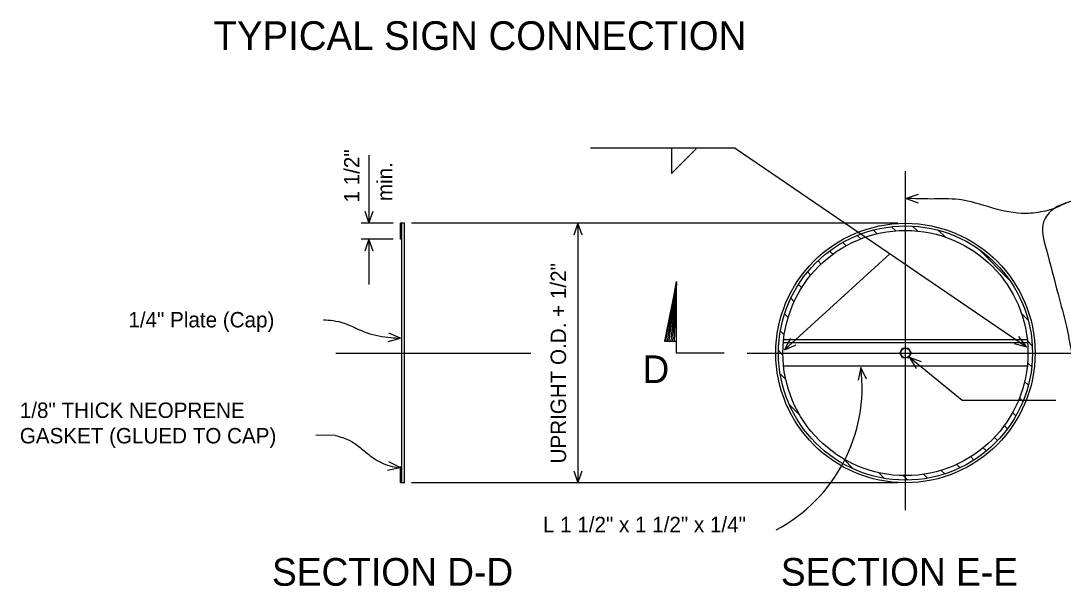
# Model space of a CAD drawing. Extents: x -211.3 to -203.73, y 425.09 to 430.2.
# Drawn here: x -206.732 to -205.177, y 426.831 to 427.674 of the extents above; entities that cross this region are included whole.
import ezdxf

# ---------------------------------------------------------------- set-up
doc = ezdxf.new("R2010")
doc.units = 0
doc.layers.add('Level 1', color=7, linetype='Continuous')
doc.layers.add('Level 2', color=7, linetype='Continuous')

msp = doc.modelspace()

# ---------------------------------------------------------------- linework, layer by layer
at = {"layer": 'Level 1'}
for p, q in [((-206.1595, 427.3722), (-206.1654, 427.3722)), ((-206.1654, 427.3485), (-206.1654, 427.3722)), ((-206.1634, 426.985), (-206.1634, 427.3722)), ((-206.1595, 426.985), (-206.1595, 427.3722)), ((-205.4543, 427.3566), (-205.4598, 427.3621)), ((-205.4265, 427.361), (-205.4326, 427.3671)), ((-205.394, 427.3607), (-205.4013, 427.3679)), ((-205.3529, 427.3518), (-205.363, 427.3618)), ((-206.1634, 427.3485), (-206.1654, 427.3485)), ((-205.5006, 427.3386), (-205.5055, 427.3435)), ((-205.4788, 427.3489), (-205.4839, 427.3541)), ((-205.5203, 427.3261), (-205.525, 427.3308)), ((-205.2575, 427.2885), (-205.3022, 427.3331)), ((-205.5378, 427.3114), (-205.5425, 427.3161)), ((-205.5533, 427.2947), (-205.558, 427.2995)), ((-205.5668, 427.2761), (-205.5716, 427.2809)), ((-205.5781, 427.2552), (-205.5831, 427.2602)), ((-205.587, 427.2318), (-205.5923, 427.2372)), ((-205.2289, 427.2276), (-205.2389, 427.2377)), ((-205.5929, 427.2056), (-205.5987, 427.2114)), ((-205.2302, 427.1983), (-205.5938, 427.1983)), ((-205.2302, 427.1939), (-205.5938, 427.1939)), ((-205.2228, 427.1893), (-205.23, 427.1966)), ((-205.5948, 427.1754), (-205.6015, 427.1821)), ((-205.4204, 427.1786), (-205.4162, 427.1858)), ((-205.4162, 427.1713), (-205.4204, 427.1786)), ((-205.4162, 427.1858), (-205.4078, 427.1858)), ((-205.4078, 427.1858), (-205.4036, 427.1786)), ((-205.4036, 427.1786), (-205.4078, 427.1713)), ((-205.2302, 427.1588), (-205.5938, 427.1588)), ((-205.4078, 427.1713), (-205.4162, 427.1713)), ((-205.2236, 427.1579), (-205.2297, 427.1641)), ((-205.5905, 427.1389), (-205.5989, 427.1473)), ((-205.2286, 427.1308), (-205.2341, 427.1363)), ((-205.2366, 427.1066), (-205.2418, 427.1118)), ((-205.5696, 427.0858), (-205.5851, 427.1012)), ((-205.2471, 427.085), (-205.252, 427.0899)), ((-205.2598, 427.0655), (-205.2646, 427.0702)), ((-205.2745, 427.048), (-205.2792, 427.0527)), ((-205.2912, 427.0325), (-205.2959, 427.0372)), ((-205.4893, 427.0054), (-205.5047, 427.0209)), ((-205.3098, 427.0189), (-205.3146, 427.0237)), ((-206.1634, 427.0087), (-206.1654, 427.0087)), ((-206.1654, 426.985), (-206.1654, 427.0087)), ((-205.3534, 426.9982), (-205.3588, 427.0035)), ((-205.3304, 427.0074), (-205.3354, 427.0124)), ((-205.4432, 426.9915), (-205.4517, 426.9999)), ((-205.4085, 426.9889), (-205.4152, 426.9956)), ((-205.3792, 426.9918), (-205.385, 426.9976)), ((-206.1595, 426.985), (-206.1654, 426.985))]:
    msp.add_line(p, q, dxfattribs=at)
for major_axis in [(0, -0.1936), (0, -0.1897), (0, -0.183), (0, 0.00715)]:
    msp.add_ellipse((-205.412, 427.1786), major_axis=major_axis, ratio=0.999338, dxfattribs=at)
at = {"layer": 'Level 2'}
for p, q in [((-205.666, 427.4845), (-205.8819, 427.4845)), ((-205.666, 427.4845), (-205.2312, 427.188)), ((-206.2128, 427.4736), (-206.2128, 427.3722)), ((-205.412, 426.944), (-205.412, 427.4499)), ((-206.1767, 427.3722), (-206.2241, 427.3722)), ((-205.4234, 427.3722), (-206.149, 427.3722)), ((-205.9007, 427.3722), (-205.9007, 426.985)), ((-206.1767, 427.3485), (-206.2241, 427.3485)), ((-206.2128, 427.3485), (-206.2128, 427.2806)), ((-205.5925, 427.1833), (-205.4354, 427.3264)), ((-205.7694, 427.1966), (-205.7538, 427.2851)), ((-205.7538, 427.2851), (-205.7676, 427.1962)), ((-205.7538, 427.2851), (-205.7651, 427.1967)), ((-205.7538, 427.2851), (-205.7623, 427.1965)), ((-205.7538, 427.2851), (-205.7596, 427.1963)), ((-205.7538, 427.2851), (-205.757, 427.1962)), ((-206.262, 427.1786), (-205.9713, 427.1786)), ((-205.6484, 427.1786), (-205.0777, 427.1786)), ((-205.412, 427.1786), (-205.412, 427.1786)), ((-205.3273, 427.1078), (-205.406, 427.1718)), ((-205.1875, 427.1078), (-205.3273, 427.1078)), ((-206.2629, 427.0557), (-206.2918, 427.0558)), ((-205.4234, 426.985), (-206.149, 426.985))]:
    msp.add_line(p, q, dxfattribs=at)
for points in [[(-205.761, 427.4844), (-205.761, 427.4467), (-205.7243, 427.4835)], [(-205.3928, 427.4151), (-205.4109, 427.4094), (-205.3931, 427.4027)], [(-205.3928, 427.4151), (-205.4109, 427.4094), (-205.3931, 427.4027)], [(-206.219, 427.3902), (-206.2128, 427.3722), (-206.2066, 427.3902)], [(-205.8944, 427.3542), (-205.9007, 427.3722), (-205.9069, 427.3542)], [(-206.2066, 427.3305), (-206.2128, 427.3485), (-206.219, 427.3305)], [(-205.6827, 427.1786), (-205.7538, 427.1786), (-205.7538, 427.2851), (-205.7715, 427.1963), (-205.7538, 427.1963)], [(-206.184, 427.1958), (-206.1656, 427.2006), (-206.1831, 427.2083)], [(-205.5834, 427.2001), (-205.5925, 427.1833), (-205.575, 427.1909)], [(-205.5834, 427.2001), (-205.5925, 427.1833), (-205.575, 427.1909)], [(-205.2496, 427.193), (-205.2312, 427.188), (-205.2426, 427.2033)], [(-205.4701, 427.1396), (-205.4784, 427.1568), (-205.4824, 427.1381)], [(-205.3881, 427.1652), (-205.406, 427.1718), (-205.396, 427.1556)], [(-206.1849, 427.004), (-206.1662, 427.0076), (-206.1831, 427.0164)], [(-205.9069, 427.003), (-205.9007, 426.985), (-205.8944, 427.003)]]:
    msp.add_lwpolyline(points, dxfattribs=at)
msp.add_ellipse((-205.7169, 427.1274), major_axis=(0, -0.2404), ratio=0.999338, start_param=0.485956, end_param=1.693058, dxfattribs=at)
for points in [[(-205.1559, 427.4075), (-205.171, 427.4028), (-205.1898, 427.3943), (-205.203, 427.3905), (-205.2322, 427.3867), (-205.283, 427.3952), (-205.3319, 427.4075), (-205.3742, 427.4084), (-205.4109, 427.4094)], [(-205.1559, 427.4075), (-205.171, 427.4028), (-205.1898, 427.3943), (-205.2058, 427.3745), (-205.2021, 427.334), (-205.1842, 427.2662), (-205.1719, 427.2182), (-205.1644, 427.1805)], [(-206.2806, 427.2281), (-206.2663, 427.227), (-206.2491, 427.2229), (-206.2154, 427.2086), (-206.1799, 427.2018), (-206.1656, 427.2006)], [(-206.2629, 427.0557), (-206.252, 427.0523), (-206.2377, 427.046), (-206.2222, 427.0346), (-206.2033, 427.0202), (-206.1782, 427.0094), (-206.1662, 427.0076)]]:
    msp.add_spline(points, degree=3, dxfattribs=at)

# ---------------------------------------------------------------- texts
for s, height, p in [('TYPICAL SIGN CONNECTION', 0.0428, (-206.4445, 427.6308)), ('1/4" Plate (Cap)', 0.023, (-206.5716, 427.2168)), ('D', 0.0414, (-205.8044, 427.1337)), ('1/8" THICK NEOPRENE', 0.023, (-206.7337, 427.0817)), ('GASKET (GLUED TO CAP)', 0.023, (-206.7337, 427.0437)), ('L 1 1/2" x 1 1/2" x 1/4"', 0.023, (-205.953, 426.9112)), ('SECTION D-D', 0.0414, (-206.3573, 426.8313)), ('SECTION E-E', 0.0414, (-205.5979, 426.8313))]:
    msp.add_text(s, height=height, dxfattribs=at).set_placement(p)
for s, p in [('1 1/2"', (-206.2268, 427.4032)), ('min.', (-206.1776, 427.4053)), ('UPRIGHT O.D. + 1/2"', (-205.9185, 427.0138))]:
    msp.add_text(s, height=0.023, rotation=90, dxfattribs=at).set_placement(p)

doc.saveas('drawing.dxf')
